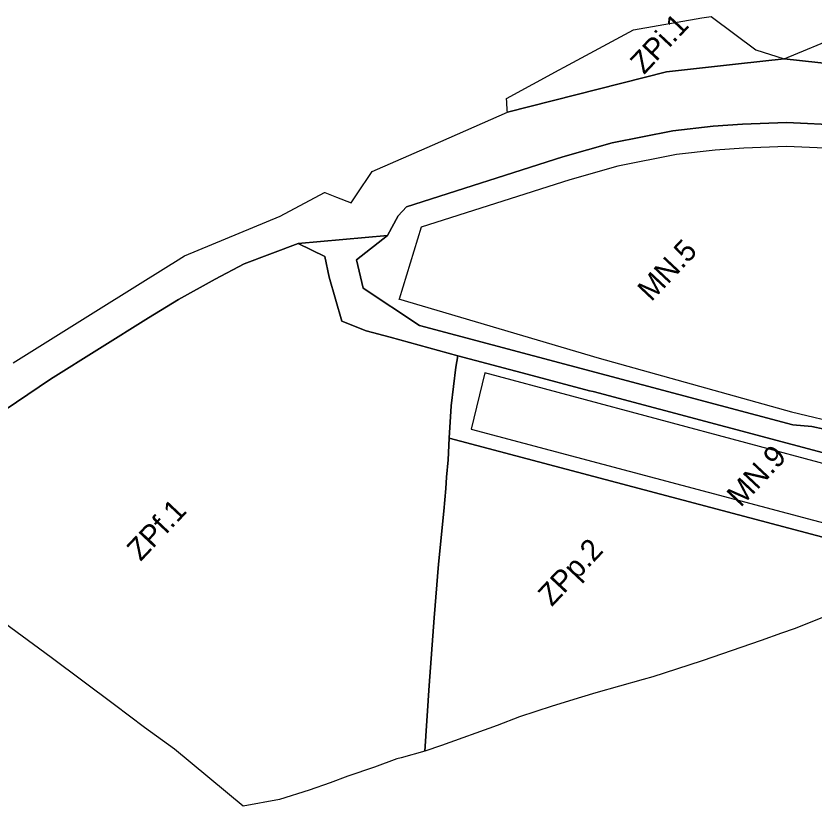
# Model space of a CAD drawing. Extents: x 7425782 to 7428854, y 5550411 to 5553074.
# Drawn here: x 7427339.3 to 7427672.4, y 5552290.4 to 5552620.2 of the extents above; entities that cross this region are included whole.
import ezdxf

# ---------------------------------------------------------------- set-up
doc = ezdxf.new("R2010")
doc.units = 0
for name, color, linetype in [('LIN_linie_rozgraniczajace', 7, 'Continuous'), ('LIN_nieprzekraczalna linia zabudowy', 7, 'Continuous'), ('TXT_oznaczenia przeznaczen', 7, 'Continuous')]:
    doc.layers.add(name, color=color, linetype=linetype)

msp = doc.modelspace()

# ---------------------------------------------------------------- linework, layer by layer
at = {"layer": 'LIN_linie_rozgraniczajace'}
for points in [[(7427659.97, 5552602.41), (7427640.88, 5552600.28), (7427610.79, 5552596.93), (7427544.45, 5552580.12), (7427544.39, 5552580.82), (7427544.13, 5552584.21), (7427544.01, 5552585.83), (7427566.07, 5552597.71), (7427568.18, 5552598.85), (7427597.07, 5552614.41), (7427625.55, 5552619.4), (7427629.41, 5552620.08), (7427630.08, 5552619.58), (7427648.07, 5552606.08)], [(7427706.13, 5552603.86), (7427720.23, 5552598.77), (7427733.95, 5552594.24), (7427659.97, 5552602.41), (7427683.49, 5552612.03)], [(7427726.52, 5552423.94), (7427719.29, 5552416.96), (7427716.55, 5552416.25), (7427713.95, 5552415.33), (7427678.18, 5552402.12), (7427520.16, 5552444.01), (7427520.89, 5552457.43), (7427522.87, 5552473.59), (7427523.81, 5552478.43), (7427552.66, 5552470.74), (7427578.67, 5552463.71), (7427580.17, 5552463.41), (7427690.89, 5552433.92)]]:
    msp.add_lwpolyline(points, close=True, dxfattribs=at)
for points in [[(7427338.21, 5552475.4), (7427373.72, 5552497.74), (7427403.06, 5552515.98), (7427405.95, 5552517.77), (7427409.68, 5552520.06), (7427449.54, 5552536.74), (7427468.09, 5552546.59), (7427468.2, 5552546.53), (7427471.73, 5552545.21), (7427473.17, 5552544.64), (7427479.25, 5552542.27), (7427481.5, 5552545.6), (7427488, 5552555.27), (7427513.1, 5552566.34), (7427544.45, 5552580.12), (7427610.79, 5552596.93), (7427640.88, 5552600.28), (7427659.97, 5552602.41), (7427733.95, 5552594.24)], [(7427684.15, 5552574.7), (7427660.88, 5552575.75), (7427642.55, 5552575.08), (7427630.24, 5552574.19), (7427613.49, 5552572.26), (7427588.14, 5552567.24), (7427567.56, 5552561.47), (7427502.33, 5552540.62), (7427498.85, 5552536.84), (7427494.38, 5552528.62), (7427457.13, 5552525.32), (7427434.64, 5552516.73), (7427422.46, 5552510.38), (7427407.24, 5552501.89), (7427394.7, 5552494.23), (7427353.75, 5552468.61), (7427334.88, 5552455.77)], [(7427676.56, 5552447.74), (7427671.54, 5552448.86), (7427663.48, 5552449.5), (7427507.72, 5552490.99), (7427484.24, 5552506.66), (7427481.43, 5552518.47), (7427494.38, 5552528.62), (7427498.85, 5552536.84), (7427502.33, 5552540.62), (7427567.56, 5552561.47), (7427588.14, 5552567.24), (7427613.49, 5552572.26), (7427630.24, 5552574.19), (7427642.55, 5552575.08), (7427660.88, 5552575.75), (7427684.15, 5552574.7)], [(7427690.89, 5552433.92), (7427580.17, 5552463.41), (7427578.67, 5552463.71), (7427552.66, 5552470.74), (7427523.81, 5552478.43), (7427495.49, 5552486.17), (7427485.43, 5552488.84), (7427475.33, 5552492.89), (7427470.03, 5552511.26), (7427468.27, 5552519.86), (7427457.13, 5552525.32), (7427494.38, 5552528.62), (7427481.43, 5552518.47), (7427484.24, 5552506.66), (7427507.72, 5552490.99), (7427663.48, 5552449.5), (7427671.54, 5552448.86), (7427676.56, 5552447.74)], [(7427334.88, 5552455.77), (7427353.75, 5552468.61), (7427394.7, 5552494.23), (7427407.24, 5552501.89), (7427422.46, 5552510.38), (7427434.64, 5552516.73), (7427457.13, 5552525.32), (7427468.27, 5552519.86), (7427470.03, 5552511.26), (7427475.33, 5552492.89), (7427485.43, 5552488.84), (7427495.49, 5552486.17), (7427523.81, 5552478.43), (7427522.87, 5552473.59), (7427520.89, 5552457.43), (7427520.16, 5552444.01), (7427519.67, 5552434.95), (7427519.01, 5552427.78), (7427518.72, 5552422.93), (7427517.83, 5552413.58), (7427515.72, 5552391.38), (7427513.82, 5552368.96), (7427511.82, 5552340.75), (7427509.92, 5552313.27), (7427500.08, 5552310.62), (7427498.29, 5552310.13), (7427488.98, 5552306.61), (7427477.89, 5552302.84), (7427470.41, 5552300.17), (7427461.68, 5552297.1), (7427449.38, 5552293.1), (7427434.16, 5552290.43), (7427405.54, 5552314.17), (7427393, 5552323.23), (7427380.44, 5552332.65), (7427354, 5552352.5), (7427310.28, 5552384.58)], [(7427706.22, 5552381.27), (7427664.06, 5552364.35), (7427658.88, 5552362.58), (7427650.26, 5552359.58), (7427625.66, 5552351.03), (7427614.98, 5552347.5), (7427605.1, 5552344.3), (7427601.09, 5552343.19), (7427581.3, 5552337.68), (7427575.4, 5552335.83), (7427563.17, 5552332.13), (7427549.44, 5552327.6), (7427540.12, 5552324.08), (7427516.86, 5552315.71), (7427509.92, 5552313.27), (7427511.82, 5552340.75), (7427513.82, 5552368.96), (7427515.72, 5552391.38), (7427517.83, 5552413.58), (7427518.72, 5552422.93), (7427519.01, 5552427.78), (7427519.67, 5552434.95), (7427520.16, 5552444.01), (7427678.18, 5552402.12)]]:
    msp.add_lwpolyline(points, dxfattribs=at)
at = {"layer": 'LIN_nieprzekraczalna linia zabudowy'}
msp.add_line((7427718.72, 5552421.94), (7427534.94, 5552471.33), dxfattribs=at)
for points in [[(7427824.92, 5552528.41), (7427819.51, 5552530.1), (7427803.54, 5552535.43), (7427778.69, 5552543.59), (7427728.41, 5552557.37), (7427705.98, 5552561.94), (7427683.31, 5552564.73), (7427660.84, 5552565.74), (7427643.09, 5552565.09), (7427631.17, 5552564.23), (7427615.03, 5552562.37), (7427590.46, 5552557.51), (7427570.44, 5552551.89), (7427508.37, 5552532.06), (7427499.23, 5552502.04)], [(7427498.98, 5552502.11), (7427582.78, 5552477.41), (7427662.97, 5552455.02)], [(7427534.94, 5552471.33), (7427529.32, 5552447.81), (7427683.09, 5552406.89), (7427715.66, 5552419.02), (7427718.72, 5552421.94)], [(7427662.97, 5552455.02), (7427685.09, 5552449.75), (7427701.4, 5552444.95), (7427741.62, 5552432.74)]]:
    msp.add_lwpolyline(points, dxfattribs=at)

# ---------------------------------------------------------------- texts
at = {"layer": 'TXT_oznaczenia przeznaczen'}
for s, p in [('ZPi.1', (7427601.44, 5552595.51)), ('MN.5', (7427604.47, 5552500.68)), ('MN.9', (7427641.73, 5552414.83)), ('ZPf.1', (7427391.36, 5552392.3)), ('ZPp.2', (7427562.95, 5552373.39))]:
    msp.add_text(s, height=9, rotation=46.7736, dxfattribs=at).set_placement(p)

doc.saveas('drawing.dxf')
